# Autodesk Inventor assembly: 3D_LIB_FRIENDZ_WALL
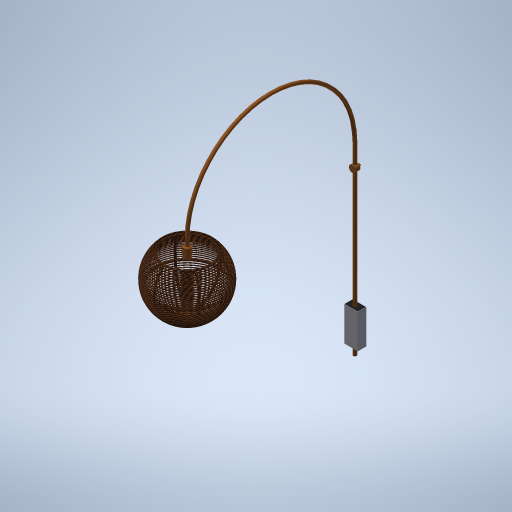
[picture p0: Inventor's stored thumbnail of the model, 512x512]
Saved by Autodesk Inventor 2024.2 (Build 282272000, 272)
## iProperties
Manager: Filip
Company: DARK
Created: 2023-07
Part Number: 3D_LIB_FRIENDZ_WALL
Document SubType Name: Assembly
Designer: Manuel
Engineer: Filip
Project: SPW1069 - FRIENDS
Description: FRIENDS WALL - Fix
Author: Manuel
Revision Number: v0
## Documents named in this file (10)
- C:\Users\Stage\Desktop\Stage Karsten\armatures\Friendz\SPW1069_KARSTEN\3D_LIB_FRIENDZ_WALL.iam
- C:\Users\Stage\Downloads\SPW1069 - FRIENDS\SPW1069-20.iam
- C:\Users\Stage\Downloads\SPW1069 - FRIENDS\351-201.ipt
- C:\Users\Stage\Downloads\SPW1069 - FRIENDS\SPW1069-002.ipt
- C:\Users\Stage\Downloads\SPW1069 - FRIENDS\SPW1069-007.ipt
- C:\Users\Stage\Downloads\SPW1069 - FRIENDS\SPW1069-008.ipt
- C:\Users\Stage\Downloads\SPW1069 - FRIENDS\SPW1069-009.ipt
- C:\Users\Stage\Downloads\SPW1069 - FRIENDS\SPW1069-010.ipt
- C:\Users\Stage\Downloads\SPW1069 - FRIENDS\SPW1069-012.ipt
- C:\Users\Stage\Downloads\SPW1069 - FRIENDS\SPW1069-013.ipt
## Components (9 placed, 9 different names)
1. SPW1069-20:1 [sub-assembly] — Mate:2, Flush:1, Mate:4, Mate:5, Mate:6, Mate:7, Flush:2
2. 351-201:1 — Mate:2, Mate:3
3. SPW1069-002:1 — Mate:4, Mate:5
4. SPW1069-007:1 — Mate:6, Mate:7, Flush:2, Angle:2, Mate:18, Mate:19, Mate:27
5. SPW1069-008:1 — Mate:13, Mate:14, Angle:2, Flush:10, Mate:20, Mate:26, Mate:27
6. SPW1069-009:1 — Mate:10, Mate:13, Mate:14, Mate:26
7. SPW1069-010:1 — Mate:10
8. SPW1069-012:1 — Flush:8, Flush:9, Mate:17
9. SPW1069-013:1 — Flush:8, Flush:9, Mate:17, Flush:10, Mate:18, Mate:19, Mate:20
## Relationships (21: Mate 15, Flush 5, Angle 1)
- Mate:2: SPW1069-20:1 ↔ 351-201:1
- Mate:3: 351-201:1
- Flush:1: SPW1069-20:1
- Mate:4: SPW1069-20:1 ↔ SPW1069-002:1
- Mate:5: SPW1069-20:1 ↔ SPW1069-002:1
- Mate:6: SPW1069-20:1 ↔ SPW1069-007:1
- Mate:7: SPW1069-20:1 ↔ SPW1069-007:1
- Flush:2: SPW1069-20:1 ↔ SPW1069-007:1
- Mate:10: SPW1069-009:1 ↔ SPW1069-010:1
- Mate:13: SPW1069-008:1 ↔ SPW1069-009:1
- Mate:14: SPW1069-008:1 ↔ SPW1069-009:1
- Angle:2: SPW1069-007:1 ↔ SPW1069-008:1
- Flush:8: SPW1069-012:1 ↔ SPW1069-013:1
- Flush:9: SPW1069-012:1 ↔ SPW1069-013:1
- Mate:17: SPW1069-012:1 ↔ SPW1069-013:1
- Flush:10: SPW1069-008:1 ↔ SPW1069-013:1
- Mate:18: SPW1069-007:1 ↔ SPW1069-013:1
- Mate:19: SPW1069-007:1 ↔ SPW1069-013:1
- Mate:20: SPW1069-008:1 ↔ SPW1069-013:1
- Mate:26: SPW1069-008:1 ↔ SPW1069-009:1
- Mate:27: SPW1069-007:1 ↔ SPW1069-008:1
